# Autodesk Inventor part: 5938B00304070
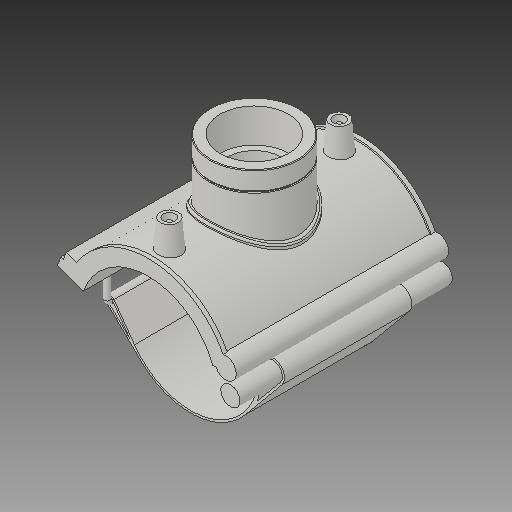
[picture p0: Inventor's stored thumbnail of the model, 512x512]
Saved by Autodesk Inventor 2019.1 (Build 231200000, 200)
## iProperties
Created: 2017-07
Part Number: 5938B00304070
Material: Generic
Description: PLASSON TRANSITION SADDLE 4''IPS x 2"NPT
Document SubType Name: Modeling
Designer: KIM
Density: 1 g/cm^3
Appearance: Default
Author: KIM
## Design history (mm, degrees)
derived "5938B.ipt"
feature "Solid1::5938B.ipt"
tag "TaggingFeature1"
body "Solid1"
other parameters: "d_" = 114.1, "B_" = 156.21, "H_" = 46.736, "L_" = 176.022, "d_t" = 6, "G_" = 56.656, "d148" = 1.7115, "d160" = 1.7115, "d169" = 1.7115, "d192" = 4.564, "d0" = 114.1, "d1" = 136.92, "d2" = 390.525, "d3" = 28.525, "d4" = 176.022, "d5" = 0, "d40" = 71.1984, "d41" = 79.3184, "d43" = 0, "d45" = 0, "d47" = 115.196, "d48" = 73.6528, "d50" = 0, "d78" = 90.46, "d79" = 15, "d80" = 70.4088, "d82" = 5 deg, "d84" = 4, "d85" = 14, "d86" = 0, "d87" = 3, "d88" = 0, "d96" = 139.6584, "d97" = 3.52044, "d98" = 0, "d102" = 1.69968, "d103" = 56.656, "d104" = 28.0416, "d105" = 0, "d106" = 45.3248, "d108" = 0, "d109" = -15.57867, "d111" = 0.5, "d112" = 0.5, "d113" = 0, "d114" = 0.5, "d117" = 0.56656, "d120" = 140 deg, "d121" = 24.228, "d122" = 20 deg, "d123" = 547.68, "d124" = 82.152, "d126" = 0, "d143" = 117.523, "d145" = 17.55385, "d149" = 1.7115, "d150" = 19.30923, "d153" = 176.022, "d154" = 0, "d156" = 68.46, "d157" = 160 deg, "d159" = 4.564, "d161" = 1.7115, "d162" = 105.6132, "d163" = 0, "d164" = 57.05, "d167" = 11.41, "d168" = 66.79024, "d170" = 1.7115, "d172" = 0, "d173" = 1, "d175" = 57.05, "d176" = 20 deg, "d177" = 7.987, "d178" = 22.82, "d180" = 0, "d183" = 9.128, "d184" = 6.3896, "d185" = 57.20715, "d186" = 57.20715, "d187" = 68.46, "d188" = 6.846, "d189" = 7.987, "d190" = 0, "d191" = 82.152, "d193" = 4.564, "d194" = 2.33905, "d195" = 90 deg, "d197" = 0, "d199" = 0
